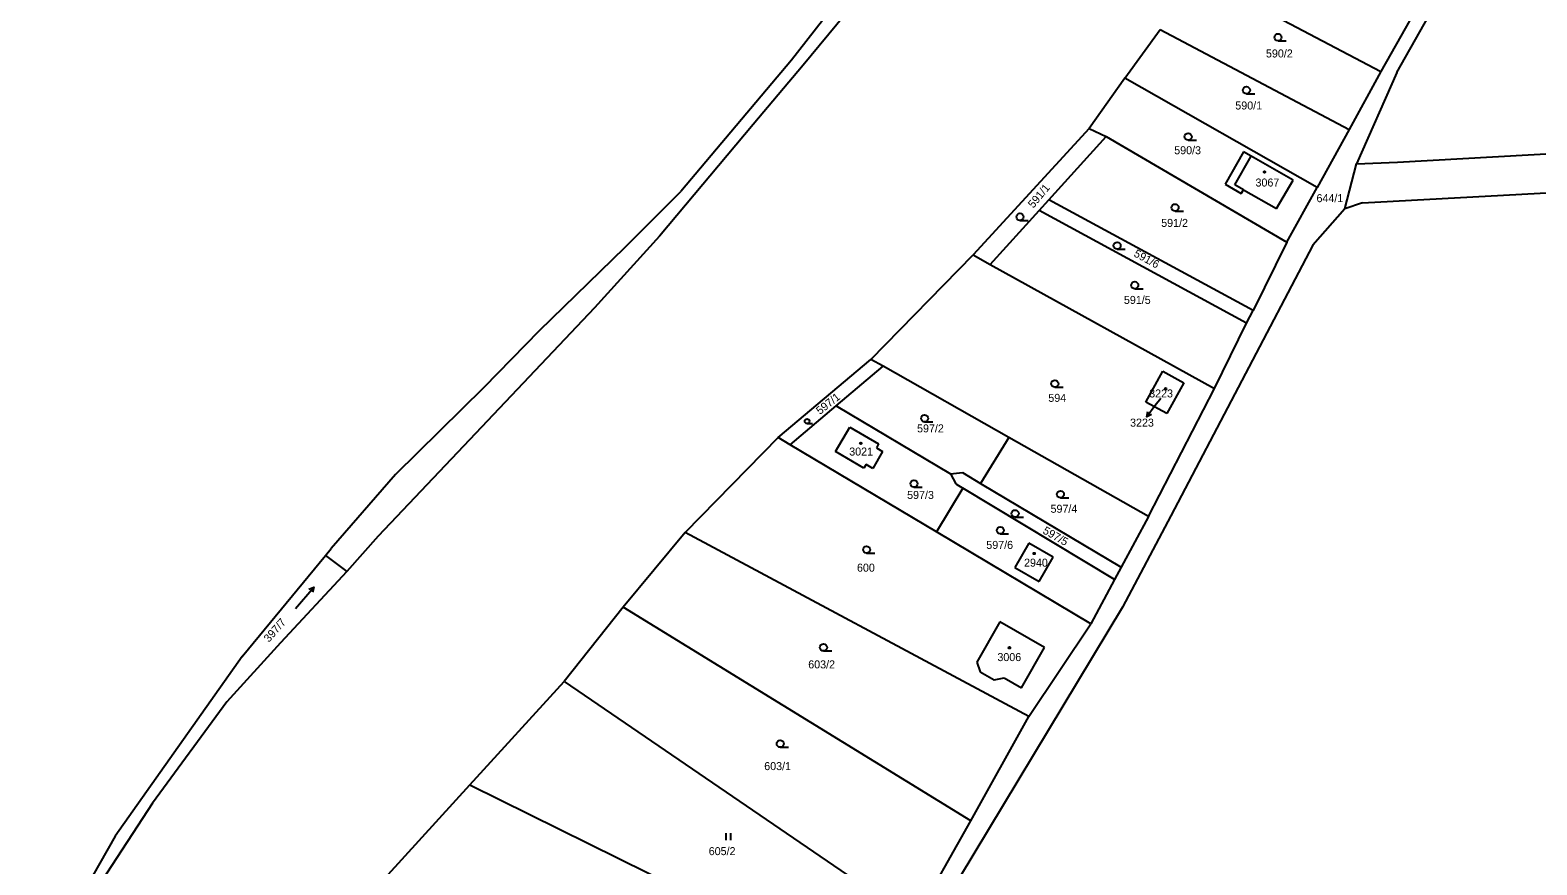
# Model space of a CAD drawing. Extents: x -735249 to -729401, y -1124843 to -1121828.
# Drawn here: x -735201 to -734880.9, y -1123604.3 to -1123427 of the extents above; entities that cross this region are included whole.
import ezdxf

# ---------------------------------------------------------------- set-up
doc = ezdxf.new("R2010")
doc.units = 0
for name, color, linetype in [('Vrstva 1', 7, 'Continuous'), ('Vrstva 13', 7, 'Continuous'), ('Vrstva 16', 7, 'Continuous'), ('Vrstva 18', 7, 'Continuous'), ('Vrstva 19', 7, 'Continuous'), ('Vrstva 25', 7, 'Continuous'), ('Vrstva 4', 7, 'Continuous')]:
    doc.layers.add(name, color=color, linetype=linetype)

msp = doc.modelspace()

# ---------------------------------------------------------------- linework, layer by layer
at = {"layer": 'Vrstva 1'}
for points in [[(-734991.43, -1123371.44), (-734989.96, -1123372.58), (-735003.91, -1123392.74), (-735012.72, -1123405.68), (-735027.95, -1123423.81), (-735036.83, -1123434.46), (-735047.41, -1123447.11), (-735067.32, -1123470.77), (-735081.1, -1123486.01), (-735108.98, -1123515.42), (-735127.06, -1123534.51), (-735133.72, -1123542.02)], [(-734890.06, -1123393.37), (-734914.09, -1123435.84)], [(-734910.67, -1123436.07), (-734887.43, -1123394.9)], [(-734952.62, -1123415.51), (-734914.09, -1123435.84)], [(-734968.44, -1123437.24), (-734960.97, -1123426.88)], [(-734960.97, -1123426.88), (-734955.98, -1123429.52)], [(-734955.98, -1123429.52), (-734920.82, -1123448.12)], [(-734914.09, -1123435.84), (-734920.82, -1123448.12)], [(-734910.67, -1123436.07), (-734919.24, -1123455.45)], [(-734968.44, -1123437.24), (-734976.02, -1123447.91)], [(-734927.58, -1123460.44), (-734968.44, -1123437.24)], [(-734910.5, -1123455.1), (-734694.76, -1123442.96)], [(-734976.02, -1123447.91), (-735000.66, -1123474.77)], [(-734984.59, -1123463.06), (-734972.45, -1123449.61)], [(-734976.02, -1123447.91), (-734972.45, -1123449.61)], [(-734972.45, -1123449.61), (-734934.02, -1123472.1)], [(-734920.82, -1123448.12), (-734927.58, -1123460.44)], [(-734943.23, -1123452.89), (-734947.13, -1123459.73)], [(-734941.62, -1123453.79), (-734943.23, -1123452.89)], [(-734932.66, -1123458.93), (-734941.62, -1123453.79)], [(-734919.24, -1123455.45), (-734910.5, -1123455.1)], [(-734917.93, -1123463.71), (-734739.59, -1123454.01)], [(-734936.23, -1123464.94), (-734932.66, -1123458.93)], [(-734947.13, -1123459.73), (-734943.71, -1123461.76)], [(-734943.71, -1123461.76), (-734943.25, -1123460.95)], [(-734943.25, -1123460.95), (-734936.23, -1123464.94)], [(-734934.02, -1123472.1), (-734927.58, -1123460.44)], [(-734997.04, -1123476.84), (-734986.64, -1123465.32)], [(-734986.64, -1123465.32), (-734984.59, -1123463.06)], [(-734942.57, -1123489.28), (-734986.64, -1123465.32)], [(-734941.22, -1123486.6), (-734984.59, -1123463.06)], [(-734921.73, -1123464.99), (-734928.54, -1123472.7)], [(-734917.93, -1123463.71), (-734921.73, -1123464.99)], [(-734934.02, -1123472.1), (-734941.22, -1123486.6)], [(-735022.41, -1123496.96), (-735000.66, -1123474.77)], [(-735000.66, -1123474.77), (-734997.04, -1123476.84)], [(-734928.54, -1123472.7), (-734958.71, -1123530.17)], [(-734997.04, -1123476.84), (-734949.43, -1123503.17)], [(-734942.57, -1123489.28), (-734941.22, -1123486.6)], [(-734949.43, -1123503.17), (-734942.57, -1123489.28)], [(-735042.11, -1123513.58), (-735022.41, -1123496.96)], [(-735019.79, -1123498.44), (-735022.41, -1123496.96)], [(-735029.76, -1123506.86), (-735019.79, -1123498.44)], [(-734993.11, -1123513.56), (-735019.79, -1123498.44)], [(-734963.97, -1123506.03), (-734960.37, -1123499.47)], [(-734960.37, -1123499.47), (-734955.94, -1123501.94)], [(-734963.46, -1123530.35), (-734949.43, -1123503.17)], [(-734955.94, -1123501.94), (-734959.52, -1123508.49)], [(-735039.53, -1123515.12), (-735029.76, -1123506.86)], [(-735029.76, -1123506.86), (-735005.46, -1123521.3)], [(-734959.52, -1123508.49), (-734963.97, -1123506.03)], [(-735042.11, -1123513.58), (-735061.84, -1123533.75)], [(-735039.53, -1123515.12), (-735042.11, -1123513.58)], [(-735029.92, -1123516.53), (-735026.85, -1123511.34)], [(-735026.85, -1123511.34), (-735020.79, -1123514.9)], [(-734993.11, -1123513.56), (-734999.11, -1123523.31)], [(-734963.46, -1123530.35), (-734993.11, -1123513.56)], [(-735008.49, -1123533.61), (-735039.53, -1123515.12)], [(-735023.88, -1123520.08), (-735029.92, -1123516.53)], [(-735019.94, -1123516.54), (-735022.03, -1123520.11)], [(-735020.79, -1123514.9), (-735021.25, -1123515.73)], [(-735021.25, -1123515.73), (-735019.94, -1123516.54)], [(-735023.4, -1123519.31), (-735023.88, -1123520.08)], [(-735022.03, -1123520.11), (-735023.4, -1123519.31)], [(-735005.46, -1123521.3), (-735002.95, -1123521.02)], [(-735005.46, -1123521.3), (-735004.39, -1123523.41)], [(-735004.39, -1123523.41), (-735002.89, -1123524.31)], [(-735002.95, -1123521.02), (-734999.11, -1123523.31)], [(-734999.11, -1123523.31), (-734969.21, -1123541.1)], [(-735002.89, -1123524.31), (-735008.49, -1123533.61)], [(-734970.62, -1123543.73), (-735002.89, -1123524.31)], [(-734963.46, -1123530.35), (-734969.21, -1123541.1)], [(-734958.71, -1123530.17), (-734968.94, -1123549.6)], [(-735061.84, -1123533.75), (-735075.02, -1123549.61)], [(-734988.82, -1123572.83), (-735061.84, -1123533.75)], [(-734975.67, -1123553.16), (-735008.49, -1123533.61)], [(-734988.84, -1123535.98), (-734991.81, -1123541.15)], [(-734983.71, -1123538.95), (-734988.84, -1123535.98)], [(-735138.28, -1123538.59), (-735133.72, -1123542.02)], [(-734986.64, -1123544.11), (-734983.71, -1123538.95)], [(-735133.72, -1123542.02), (-735147.88, -1123557.17)], [(-734991.81, -1123541.15), (-734986.64, -1123544.11)], [(-734969.21, -1123541.1), (-734970.62, -1123543.73)], [(-734970.62, -1123543.73), (-734975.67, -1123553.16)], [(-735075.02, -1123549.61), (-735087.57, -1123565.38)], [(-735001.15, -1123594.94), (-735075.02, -1123549.61)], [(-734968.94, -1123549.6), (-735010.11, -1123617.82)], [(-734994.99, -1123552.67), (-734999.91, -1123561.28)], [(-734985.51, -1123558.12), (-734994.99, -1123552.67)], [(-734988.82, -1123572.83), (-734975.67, -1123553.16)], [(-735147.88, -1123557.17), (-735159.22, -1123569.66), (-735175.07, -1123591.23)], [(-734990.44, -1123566.7), (-734985.51, -1123558.12)], [(-734999.91, -1123561.28), (-734999.16, -1123563.3)], [(-734999.16, -1123563.3), (-734996.23, -1123564.99)], [(-734996.23, -1123564.99), (-734994.07, -1123564.61)], [(-734994.07, -1123564.61), (-734990.44, -1123566.7)], [(-735107.63, -1123587.35), (-735087.57, -1123565.38)], [(-735087.57, -1123565.38), (-735013.12, -1123616.2)], [(-735001.15, -1123594.94), (-734988.82, -1123572.83)], [(-735124.97, -1123606.35), (-735107.63, -1123587.35)], [(-735107.63, -1123587.35), (-735019.25, -1123631.03)], [(-735175.07, -1123591.23), (-735185.79, -1123607.72), (-735196.73, -1123624.62)], [(-735013.12, -1123616.2), (-735001.15, -1123594.94)]]:
    msp.add_lwpolyline(points, dxfattribs=at)
at = {"layer": 'Vrstva 13'}
for points in [[(-734997.79, -1123380.27), (-735039.26, -1123433.45)], [(-735039.26, -1123433.45), (-735062.79, -1123461.31)], [(-735070.45, -1123468.98), (-735062.79, -1123461.31)], [(-735074.77, -1123473.31), (-735070.45, -1123468.98)], [(-735074.77, -1123473.31), (-735092.87, -1123490.88)], [(-735092.87, -1123490.88), (-735104.66, -1123502.97)], [(-735104.66, -1123502.97), (-735123.38, -1123521.39)], [(-735123.38, -1123521.39), (-735137.07, -1123537.13)], [(-735156.02, -1123560.04), (-735138.28, -1123538.59)], [(-735138.28, -1123538.59), (-735137.07, -1123537.13)], [(-735156.02, -1123560.04), (-735182.96, -1123598.22)], [(-735182.96, -1123598.22), (-735201.04, -1123630.01)]]:
    msp.add_lwpolyline(points, dxfattribs=at)
at = {"layer": 'Vrstva 16'}
msp.add_lwpolyline([(-734960.83, -1123505.25), (-734961.98, -1123506.76)], dxfattribs=at)
at = {"layer": 'Vrstva 25'}
for points in [[(-734935.91, -1123429.3), (-734934.16, -1123429.3)], [(-734942.61, -1123440.55), (-734940.86, -1123440.55)], [(-734955, -1123450.43), (-734953.25, -1123450.43)], [(-734957.77, -1123465.47), (-734956.02, -1123465.47)], [(-734990.74, -1123467.45), (-734988.99, -1123467.45)], [(-734970.1, -1123473.56), (-734968.35, -1123473.56)], [(-734966.34, -1123481.96), (-734964.59, -1123481.96)], [(-734983.33, -1123502.89), (-734981.58, -1123502.89)], [(-734961.98, -1123506.76), (-734963.797, -1123509.146)], [(-735035.97, -1123510.61), (-735034.797, -1123510.61)], [(-735011, -1123510.26), (-735009.25, -1123510.26)], [(-734962.794, -1123508.653), (-734963.797, -1123509.146), (-734963.589, -1123508.047)], [(-735013.25, -1123524.1), (-735011.5, -1123524.1)], [(-734982.13, -1123526.36), (-734980.38, -1123526.36)], [(-734991.76, -1123530.46), (-734990.01, -1123530.46)], [(-734994.91, -1123534.03), (-734993.16, -1123534.03)], [(-735023.32, -1123538.14), (-735021.57, -1123538.14)], [(-735144.684, -1123549.874), (-735140.796, -1123545.306)], [(-735141.825, -1123545.743), (-735140.796, -1123545.306), (-735141.063, -1123546.391)], [(-735032.48, -1123558.89), (-735030.73, -1123558.89)], [(-735041.67, -1123579.35), (-735039.92, -1123579.35)], [(-735053.167, -1123599.075), (-735053.167, -1123597.575)], [(-735052.133, -1123599.075), (-735052.133, -1123597.575)]]:
    msp.add_lwpolyline(points, dxfattribs=at)
for centre, radius in [((-734935.91, -1123428.55), 0.75), ((-734942.61, -1123439.8), 0.75), ((-734955, -1123449.68), 0.75), ((-734938.78, -1123457.16), 0.175), ((-734957.77, -1123464.72), 0.75), ((-734990.74, -1123466.7), 0.75), ((-734970.1, -1123472.81), 0.75), ((-734966.34, -1123481.21), 0.75), ((-734983.33, -1123502.14), 0.75), ((-734959.77, -1123503.21), 0.175), ((-735035.97, -1123510.107), 0.503), ((-735011, -1123509.51), 0.75), ((-735024.56, -1123514.81), 0.175), ((-735013.25, -1123523.35), 0.75), ((-734982.13, -1123525.61), 0.75), ((-734991.76, -1123529.71), 0.75), ((-734994.91, -1123533.28), 0.75), ((-735023.32, -1123537.39), 0.75), ((-734987.72, -1123538.19), 0.175), ((-735032.48, -1123558.14), 0.75), ((-734992.97, -1123558.22), 0.175), ((-735041.67, -1123578.6), 0.75)]:
    msp.add_circle(centre, radius, dxfattribs=at)
at = {"layer": 'Vrstva 4'}
for points in [[(-734945.1, -1123459.89), (-734941.62, -1123453.79)], [(-734921.73, -1123464.99), (-734919.24, -1123455.45)], [(-734943.25, -1123460.95), (-734945.1, -1123459.89)]]:
    msp.add_lwpolyline(points, dxfattribs=at)

# ---------------------------------------------------------------- texts
at = {"layer": 'Vrstva 16'}
msp.add_text('3223', height=1.7, dxfattribs=at).set_placement((-734967.343, -1123511.25))
at = {"layer": 'Vrstva 18'}
for s, p in [('590/2', (-734938.47, -1123432.85)), ('590/1', (-734944.98, -1123443.9)), ('590/3', (-734957.96, -1123453.4)), ('644/1', (-734927.73, -1123463.58)), ('591/2', (-734960.73, -1123468.83)), ('591/5', (-734968.65, -1123485.19)), ('594', (-734984.71, -1123505.99)), ('597/2', (-735012.6, -1123512.47)), ('597/3', (-735014.71, -1123526.61)), ('597/4', (-734984.24, -1123529.54)), ('597/6', (-734997.89, -1123537.22)), ('600', (-735025.36, -1123542.05)), ('603/2', (-735035.72, -1123562.59)), ('603/1', (-735045.07, -1123584.19)), ('605/2', (-735056.86, -1123602.25))]:
    msp.add_text(s, height=1.7, dxfattribs=at).set_placement(p)
for s, rotation, p in [('591/1', 50.2004, (-734987.895, -1123464.969)), ('591/6', 331.50264, (-734966.709, -1123475)), ('597/1', 38.30031, (-735033.228, -1123508.79)), ('597/5', 330.20263, (-734986.048, -1123533.816)), ('397/7', 48.60039, (-735150.31, -1123557.174))]:
    msp.add_text(s, height=1.7, rotation=rotation, dxfattribs=at).set_placement(p)
at = {"layer": 'Vrstva 19'}
for s, p in [('3067', (-734940.69, -1123460.26)), ('3223', (-734963.283, -1123505.05)), ('3021', (-735027.01, -1123517.39)), ('2940', (-734989.87, -1123540.99)), ('3006', (-734995.53, -1123561.04))]:
    msp.add_text(s, height=1.7, dxfattribs=at).set_placement(p)

doc.saveas('drawing.dxf')
